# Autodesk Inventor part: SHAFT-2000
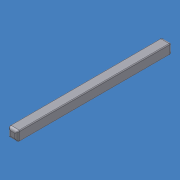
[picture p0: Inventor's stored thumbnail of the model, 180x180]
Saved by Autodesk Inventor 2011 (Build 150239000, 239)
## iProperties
Created: 2007-10
Part Number: SHAFT-2000
Document SubType Name: Modeling
Material: Steel
Density: 7.85 g/cm^3
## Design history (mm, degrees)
feature "Base1"
body "Solid1"
